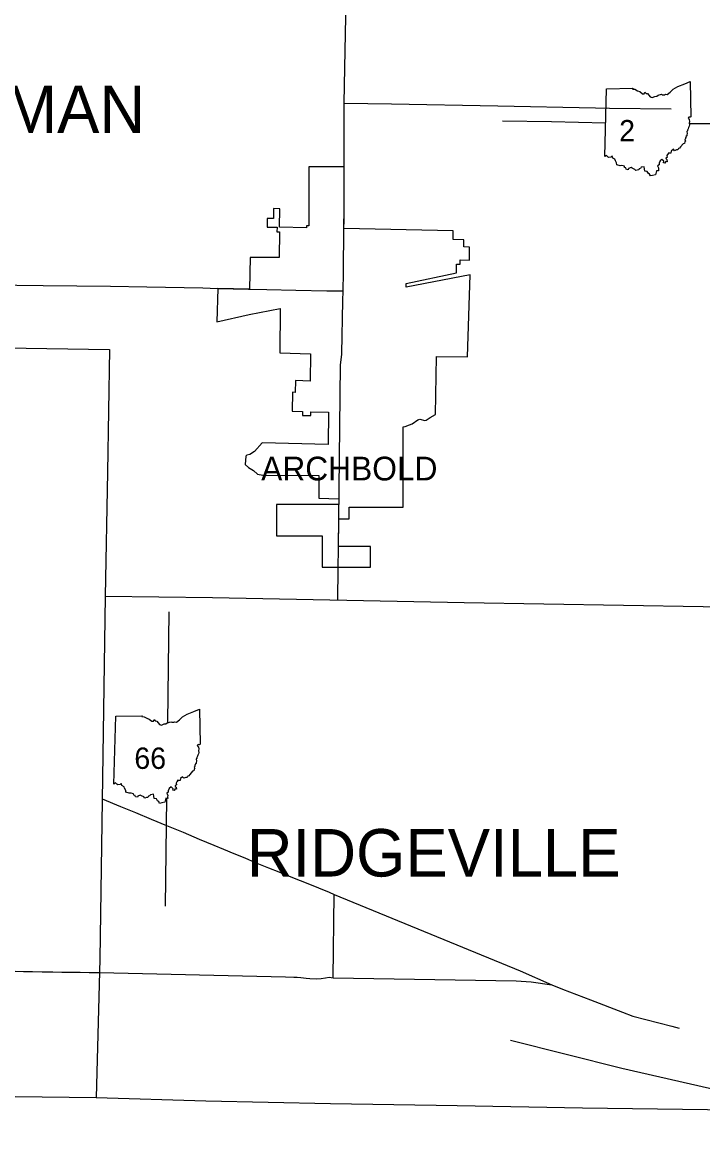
# Model space of a CAD drawing. Extents: x -232 to 448, y 619 to 1059.
# Drawn here: x -55.4 to -25.97, y 848.36 to 896.53 of the extents above; entities that cross this region are included whole.
import ezdxf

# ---------------------------------------------------------------- set-up
doc = ezdxf.new("R2010")
doc.units = 0
doc.layers.add('Default', color=7, linetype='Continuous')

msp = doc.modelspace()

# ---------------------------------------------------------------- linework, layer by layer
at = {"layer": 'Default'}
for p, q in [((-30.21, 890.731), (-30.128, 893.66)), ((-30.21, 890.731), (-30.128, 893.66)), ((-44.534, 888.477), (-44.54, 888.054)), ((-44.267, 888.473), (-44.534, 888.477)), ((-44.278, 887.672), (-44.267, 888.473)), ((-44.383, 887.674), (-44.385, 887.481)), ((-44.385, 887.481), (-44.281, 887.479)), ((-44.281, 887.479), (-44.295, 886.361)), ((-46.991, 883.585), (-45.585, 883.897)), ((-43.282, 879.709), (-43.284, 879.541)), ((-43.284, 879.541), (-42.919, 879.538)), ((-42.919, 879.538), (-42.918, 879.697)), ((-42.918, 879.697), (-42.161, 879.671)), ((-38.928, 875.564), (-38.928, 879.051)), ((-45.019, 878.35), (-45.355, 877.976)), ((-42.166, 878.284), (-45.019, 878.35)), ((-45.692, 877.819), (-45.738, 877.776)), ((-45.556, 877.846), (-45.692, 877.819)), ((-45.355, 877.976), (-45.556, 877.846)), ((-45.738, 877.776), (-45.757, 877.421)), ((-45.757, 877.421), (-45.617, 877.291)), ((-45.617, 877.291), (-45.393, 877.151)), ((-45.393, 877.151), (-45.231, 876.997)), ((-45.231, 876.997), (-44.992, 876.961)), ((-44.992, 876.961), (-42.573, 876.947)), ((-42.573, 876.947), (-42.573, 875.957)), ((-42.573, 875.957), (-41.702, 875.931)), ((-41.256, 875.06), (-41.256, 875.564)), ((-41.256, 875.564), (-38.928, 875.564)), ((-41.712, 875.06), (-41.256, 875.06)), ((-51.436, 863.603), (-51.354, 866.532)), ((-51.436, 863.603), (-51.354, 866.532))]:
    msp.add_line(p, q, dxfattribs=at)
for points in [[(-41.476, 893.037), (-41.452, 894.56), (-41.397, 897.519), (-41.385, 898.478)], [(-30.128, 893.66), (-28.992, 893.679), (-29.01, 893.644), (-28.902, 893.636), (-28.788, 893.574), (-28.692, 893.534), (-28.574, 893.441), (-28.504, 893.442), (-28.474, 893.519), (-28.42, 893.46), (-28.356, 893.449), (-28.245, 893.309), (-28.154, 893.279), (-28.044, 893.327), (-27.962, 893.334), (-27.902, 893.382), (-27.746, 893.423), (-27.703, 893.398), (-27.62, 893.403), (-27.579, 893.421), (-27.507, 893.405), (-27.38, 893.512), (-27.25, 893.637), (-27.049, 893.756), (-26.749, 893.868), (-26.512, 893.968), (-26.478, 892.448)], [(-30.128, 893.66), (-28.992, 893.679), (-29.01, 893.644), (-28.902, 893.636), (-28.788, 893.574), (-28.692, 893.534), (-28.574, 893.441), (-28.504, 893.442), (-28.474, 893.519), (-28.42, 893.46), (-28.356, 893.449), (-28.245, 893.309), (-28.154, 893.279), (-28.044, 893.327), (-27.962, 893.334), (-27.902, 893.382), (-27.746, 893.423), (-27.703, 893.398), (-27.62, 893.403), (-27.579, 893.421), (-27.507, 893.405), (-27.38, 893.512), (-27.25, 893.637), (-27.049, 893.756), (-26.749, 893.868), (-26.512, 893.968), (-26.478, 892.448)], [(-41.475, 890.238), (-41.473, 890.665), (-41.478, 892.503), (-41.476, 893.037)], [(-41.476, 893.037), (-39.437, 893.009), (-34.838, 892.926), (-30.61, 892.834), (-30.009, 892.826)], [(-30.009, 892.826), (-27.335, 892.793)], [(-34.637, 892.276), (-32.508, 892.249), (-30.169, 892.193)], [(-26.478, 892.448), (-26.513, 892.427), (-26.567, 892.437), (-26.604, 892.394), (-26.559, 892.323), (-26.537, 892.248), (-26.556, 892.165), (-26.537, 892.097), (-26.55, 892.04), (-26.584, 891.983), (-26.596, 891.929), (-26.625, 891.872), (-26.623, 891.84), (-26.651, 891.814), (-26.646, 891.719), (-26.66, 891.666), (-26.655, 891.621), (-26.7, 891.609), (-26.689, 891.572), (-26.718, 891.543), (-26.712, 891.493), (-26.744, 891.461), (-26.713, 891.397), (-26.738, 891.377), (-26.759, 891.299), (-26.817, 891.284), (-26.933, 891.142), (-26.973, 891.088), (-27.019, 891.075), (-27.044, 891.02), (-27.101, 891.019), (-27.186, 890.981), (-27.241, 891.047), (-27.338, 890.968), (-27.349, 890.877), (-27.471, 890.879), (-27.467, 890.833), (-27.494, 890.82), (-27.519, 890.774), (-27.504, 890.691), (-27.562, 890.67), (-27.555, 890.623), (-27.518, 890.594), (-27.502, 890.502), (-27.562, 890.521), (-27.612, 890.444), (-27.664, 890.462), (-27.647, 890.527), (-27.733, 890.605), (-27.815, 890.543), (-27.858, 890.442), (-27.858, 890.375), (-27.919, 890.334), (-27.88, 890.239), (-27.888, 890.173), (-27.886, 890.111), (-27.963, 890.113), (-28.009, 889.945)], [(-26.478, 892.448), (-26.513, 892.427), (-26.567, 892.437), (-26.604, 892.394), (-26.559, 892.323), (-26.537, 892.248), (-26.556, 892.165), (-26.537, 892.097), (-26.55, 892.04), (-26.584, 891.983), (-26.596, 891.929), (-26.625, 891.872), (-26.623, 891.84), (-26.651, 891.814), (-26.646, 891.719), (-26.66, 891.666), (-26.655, 891.621), (-26.7, 891.609), (-26.689, 891.572), (-26.718, 891.543), (-26.712, 891.493), (-26.744, 891.461), (-26.713, 891.397), (-26.738, 891.377), (-26.759, 891.299), (-26.817, 891.284), (-26.933, 891.142), (-26.973, 891.088), (-27.019, 891.075), (-27.044, 891.02), (-27.101, 891.019), (-27.186, 890.981), (-27.241, 891.047), (-27.338, 890.968), (-27.349, 890.877), (-27.471, 890.879), (-27.467, 890.833), (-27.494, 890.82), (-27.519, 890.774), (-27.504, 890.691), (-27.562, 890.67), (-27.555, 890.623), (-27.518, 890.594), (-27.502, 890.502), (-27.562, 890.521), (-27.612, 890.444), (-27.664, 890.462), (-27.647, 890.527), (-27.733, 890.605), (-27.815, 890.543), (-27.858, 890.442), (-27.858, 890.375), (-27.919, 890.334), (-27.88, 890.239), (-27.888, 890.173), (-27.886, 890.111), (-27.963, 890.113), (-28.009, 889.945)], [(-26.556, 892.164), (-24.693, 892.155), (-22.517, 892.128), (-20.083, 892.102), (-16.53, 892.06)], [(-28.009, 889.945), (-28.141, 889.913), (-28.233, 889.894), (-28.266, 889.97), (-28.332, 890.01), (-28.375, 890.087), (-28.469, 890.098), (-28.492, 890.203), (-28.502, 890.289), (-28.631, 890.268), (-28.667, 890.216), (-28.713, 890.202), (-28.739, 890.149), (-28.802, 890.144), (-28.869, 890.119), (-28.913, 890.171), (-29.023, 890.223), (-29.072, 890.25), (-29.175, 890.208), (-29.197, 890.159), (-29.28, 890.181), (-29.299, 890.236), (-29.349, 890.252), (-29.36, 890.311), (-29.466, 890.342), (-29.547, 890.329), (-29.691, 890.376), (-29.699, 890.453), (-29.748, 890.547), (-29.774, 890.612), (-29.864, 890.661), (-29.883, 890.738), (-29.912, 890.736), (-29.938, 890.705), (-30.039, 890.69), (-30.079, 890.722), (-30.136, 890.776), (-30.21, 890.731)], [(-28.009, 889.945), (-28.141, 889.913), (-28.233, 889.894), (-28.266, 889.97), (-28.332, 890.01), (-28.375, 890.087), (-28.469, 890.098), (-28.492, 890.203), (-28.502, 890.289), (-28.631, 890.268), (-28.667, 890.216), (-28.713, 890.202), (-28.739, 890.149), (-28.802, 890.144), (-28.869, 890.119), (-28.913, 890.171), (-29.023, 890.223), (-29.072, 890.25), (-29.175, 890.208), (-29.197, 890.159), (-29.28, 890.181), (-29.299, 890.236), (-29.349, 890.252), (-29.36, 890.311), (-29.466, 890.342), (-29.547, 890.329), (-29.691, 890.376), (-29.699, 890.453), (-29.748, 890.547), (-29.774, 890.612), (-29.864, 890.661), (-29.883, 890.738), (-29.912, 890.736), (-29.938, 890.705), (-30.039, 890.69), (-30.079, 890.722), (-30.136, 890.776), (-30.21, 890.731)], [(-41.475, 890.283), (-43.003, 890.283), (-43.003, 887.728)], [(-41.489, 887.495), (-41.483, 888.094), (-41.476, 890.073)], [(-41.488, 887.618), (-41.479, 888.484), (-41.476, 889.785), (-41.475, 890.283)], [(-41.476, 890.073), (-41.475, 890.183)], [(-41.475, 890.183), (-41.475, 890.238)], [(-44.54, 888.054), (-44.814, 888.054), (-44.814, 887.682)], [(-44.814, 887.682), (-44.383, 887.674)], [(-43.114, 887.652), (-44.278, 887.672)], [(-43.003, 887.728), (-43.114, 887.728), (-43.114, 887.652)], [(-41.51, 885.705), (-41.503, 886.236), (-41.493, 887.11), (-41.489, 887.495)], [(-36.758, 887.517), (-41.488, 887.618)], [(-36.053, 886.814), (-36.302, 886.822), (-36.302, 887.13), (-36.758, 887.146), (-36.758, 887.517)], [(-36.057, 886.244), (-36.053, 886.814)], [(-44.295, 886.361), (-45.55, 886.362), (-45.569, 884.994)], [(-38.79, 885.243), (-36.622, 885.697), (-36.622, 886.076), (-36.468, 886.073), (-36.468, 886.258), (-36.057, 886.244)], [(-41.521, 884.923), (-41.51, 885.705)], [(-36.028, 885.62), (-38.79, 885.075), (-38.79, 885.243)], [(-36.149, 882.065), (-36.028, 885.62)], [(-62.411, 885.218), (-60.819, 885.234), (-59.99, 885.206), (-59.711, 885.198), (-57.944, 885.192), (-54.499, 885.158), (-51.585, 885.128), (-50.017, 885.099), (-47.59, 885.046), (-46.955, 885.03)], [(-46.941, 885.029), (-46.991, 883.585)], [(-46.955, 885.03), (-45.609, 884.995)], [(-45.569, 884.994), (-46.941, 885.029)], [(-45.609, 884.995), (-44.818, 884.974), (-43.564, 884.951)], [(-43.564, 884.951), (-42.225, 884.925), (-41.521, 884.923)], [(-41.531, 884.49), (-41.521, 884.923)], [(-45.585, 883.897), (-44.241, 884.153), (-44.266, 882.238)], [(-41.585, 882.217), (-41.531, 884.49)], [(-62.463, 882.554), (-51.629, 882.386), (-51.711, 877.081), (-51.822, 871.726)], [(-44.266, 882.238), (-42.936, 882.205), (-42.947, 881.019)], [(-41.712, 875.023), (-41.641, 881.725), (-41.586, 882.168), (-41.585, 882.217)], [(-37.532, 879.571), (-37.488, 882.091)], [(-37.488, 882.091), (-36.149, 882.065)], [(-42.947, 881.019), (-43.589, 881.041), (-43.598, 880.533), (-43.709, 880.537), (-43.723, 879.725), (-43.282, 879.709)], [(-42.161, 879.671), (-42.166, 878.284)], [(-38.928, 879.051), (-38.836, 879.056), (-38.655, 879.135), (-38.535, 879.168), (-38.293, 879.342), (-38.199, 879.374), (-37.995, 879.324), (-37.929, 879.339), (-37.754, 879.441), (-37.532, 879.571)], [(-41.702, 875.931), (-41.705, 875.689)], [(-41.705, 875.689), (-44.411, 875.689), (-44.411, 874.33), (-42.432, 874.33)], [(-41.725, 873.833), (-41.712, 875.023)], [(-41.724, 873.869), (-41.712, 875.06)], [(-42.432, 874.33), (-42.432, 872.973)], [(-42.432, 872.973), (-40.344, 872.973), (-40.344, 873.869), (-41.724, 873.869)], [(-41.735, 872.912), (-41.725, 873.833)], [(-41.749, 871.559), (-41.735, 872.912)], [(-51.822, 871.726), (-52.048, 856.032), (-52.202, 850.044)], [(-51.822, 871.726), (-47.172, 871.662), (-36.289, 871.455), (-25.953, 871.278), (-20.047, 871.155)], [(-49.111, 866.258), (-49.051, 871.042)], [(-51.354, 866.532), (-50.218, 866.551), (-50.235, 866.516), (-50.128, 866.508), (-50.014, 866.446), (-49.918, 866.406), (-49.8, 866.313), (-49.73, 866.314), (-49.7, 866.39), (-49.646, 866.331), (-49.582, 866.321), (-49.471, 866.181), (-49.38, 866.15), (-49.27, 866.198), (-49.188, 866.206), (-49.128, 866.254), (-48.972, 866.294), (-48.929, 866.27), (-48.846, 866.275), (-48.805, 866.293), (-48.733, 866.277), (-48.606, 866.383), (-48.476, 866.509), (-48.275, 866.627), (-47.975, 866.74), (-47.738, 866.84), (-47.704, 865.32)], [(-51.354, 866.532), (-50.218, 866.551), (-50.235, 866.516), (-50.128, 866.508), (-50.014, 866.446), (-49.918, 866.406), (-49.8, 866.313), (-49.73, 866.314), (-49.7, 866.39), (-49.646, 866.331), (-49.582, 866.321), (-49.471, 866.181), (-49.38, 866.15), (-49.27, 866.198), (-49.188, 866.206), (-49.128, 866.254), (-48.972, 866.294), (-48.929, 866.27), (-48.846, 866.275), (-48.805, 866.293), (-48.733, 866.277), (-48.606, 866.383), (-48.476, 866.509), (-48.275, 866.627), (-47.975, 866.74), (-47.738, 866.84), (-47.704, 865.32)], [(-47.704, 865.32), (-47.739, 865.299), (-47.793, 865.309), (-47.83, 865.266), (-47.784, 865.195), (-47.763, 865.12), (-47.782, 865.037), (-47.763, 864.969), (-47.776, 864.912), (-47.81, 864.855), (-47.822, 864.8), (-47.851, 864.743), (-47.849, 864.711), (-47.877, 864.686), (-47.872, 864.591), (-47.886, 864.538), (-47.881, 864.493), (-47.926, 864.481), (-47.915, 864.443), (-47.944, 864.414), (-47.938, 864.364), (-47.97, 864.333), (-47.939, 864.269), (-47.964, 864.249), (-47.985, 864.171), (-48.043, 864.155), (-48.158, 864.014), (-48.199, 863.96), (-48.245, 863.947), (-48.27, 863.891), (-48.327, 863.891), (-48.412, 863.853), (-48.467, 863.919), (-48.564, 863.84), (-48.575, 863.748), (-48.697, 863.751), (-48.693, 863.705), (-48.72, 863.692), (-48.745, 863.645), (-48.73, 863.563), (-48.787, 863.542), (-48.781, 863.495), (-48.744, 863.465), (-48.728, 863.374), (-48.788, 863.393), (-48.838, 863.316), (-48.889, 863.334), (-48.873, 863.399), (-48.959, 863.477), (-49.041, 863.415), (-49.084, 863.314), (-49.084, 863.247), (-49.145, 863.206), (-49.106, 863.111), (-49.113, 863.045), (-49.112, 862.983), (-49.189, 862.985), (-49.235, 862.817)], [(-47.704, 865.32), (-47.739, 865.299), (-47.793, 865.309), (-47.83, 865.266), (-47.784, 865.195), (-47.763, 865.12), (-47.782, 865.037), (-47.763, 864.969), (-47.776, 864.912), (-47.81, 864.855), (-47.822, 864.8), (-47.851, 864.743), (-47.849, 864.711), (-47.877, 864.686), (-47.872, 864.591), (-47.886, 864.538), (-47.881, 864.493), (-47.926, 864.481), (-47.915, 864.443), (-47.944, 864.414), (-47.938, 864.364), (-47.97, 864.333), (-47.939, 864.269), (-47.964, 864.249), (-47.985, 864.171), (-48.043, 864.155), (-48.158, 864.014), (-48.199, 863.96), (-48.245, 863.947), (-48.27, 863.891), (-48.327, 863.891), (-48.412, 863.853), (-48.467, 863.919), (-48.564, 863.84), (-48.575, 863.748), (-48.697, 863.751), (-48.693, 863.705), (-48.72, 863.692), (-48.745, 863.645), (-48.73, 863.563), (-48.787, 863.542), (-48.781, 863.495), (-48.744, 863.465), (-48.728, 863.374), (-48.788, 863.393), (-48.838, 863.316), (-48.889, 863.334), (-48.873, 863.399), (-48.959, 863.477), (-49.041, 863.415), (-49.084, 863.314), (-49.084, 863.247), (-49.145, 863.206), (-49.106, 863.111), (-49.113, 863.045), (-49.112, 862.983), (-49.189, 862.985), (-49.235, 862.817)], [(-49.235, 862.817), (-49.367, 862.785), (-49.459, 862.766), (-49.492, 862.842), (-49.558, 862.882), (-49.601, 862.959), (-49.695, 862.97), (-49.717, 863.075), (-49.728, 863.161), (-49.857, 863.14), (-49.893, 863.087), (-49.939, 863.073), (-49.965, 863.021), (-50.028, 863.016), (-50.095, 862.991), (-50.139, 863.043), (-50.249, 863.095), (-50.298, 863.122), (-50.401, 863.08), (-50.423, 863.031), (-50.505, 863.053), (-50.525, 863.108), (-50.574, 863.124), (-50.585, 863.182), (-50.692, 863.214), (-50.773, 863.201), (-50.917, 863.248), (-50.925, 863.325), (-50.974, 863.418), (-51, 863.483), (-51.09, 863.533), (-51.109, 863.61), (-51.138, 863.608), (-51.164, 863.577), (-51.265, 863.562), (-51.305, 863.594), (-51.362, 863.648), (-51.436, 863.603)], [(-49.235, 862.817), (-49.367, 862.785), (-49.459, 862.766), (-49.492, 862.842), (-49.558, 862.882), (-49.601, 862.959), (-49.695, 862.97), (-49.717, 863.075), (-49.728, 863.161), (-49.857, 863.14), (-49.893, 863.087), (-49.939, 863.073), (-49.965, 863.021), (-50.028, 863.016), (-50.095, 862.991), (-50.139, 863.043), (-50.249, 863.095), (-50.298, 863.122), (-50.401, 863.08), (-50.423, 863.031), (-50.505, 863.053), (-50.525, 863.108), (-50.574, 863.124), (-50.585, 863.182), (-50.692, 863.214), (-50.773, 863.201), (-50.917, 863.248), (-50.925, 863.325), (-50.974, 863.418), (-51, 863.483), (-51.09, 863.533), (-51.109, 863.61), (-51.138, 863.608), (-51.164, 863.577), (-51.265, 863.562), (-51.305, 863.594), (-51.362, 863.648), (-51.436, 863.603)], [(-51.948, 862.967), (-51.146, 862.631), (-50.498, 862.364), (-49.829, 862.09), (-49.156, 861.802), (-48.442, 861.514), (-47.751, 861.217), (-47.112, 860.964), (-46.704, 860.793), (-46.256, 860.598), (-45.778, 860.406), (-45.322, 860.203), (-44.748, 859.986), (-44.301, 859.804), (-43.708, 859.564), (-43.055, 859.305), (-42.594, 859.114), (-42.133, 858.927), (-41.909, 858.833), (-33.871, 855.527), (-32.498, 854.914)], [(-49.21, 858.316), (-49.152, 862.984)], [(-41.955, 855.227), (-41.909, 858.833)], [(-55.709, 855.507), (-55.349, 855.5), (-54.952, 855.494), (-54.537, 855.487), (-54.085, 855.481), (-53.689, 855.473), (-53.276, 855.471), (-52.897, 855.463), (-52.509, 855.457), (-52.063, 855.454)], [(-52.063, 855.454), (-44.018, 855.265), (-43.66, 855.255), (-43.51, 855.25), (-43.346, 855.232), (-43.124, 855.204), (-42.964, 855.194), (-42.694, 855.178), (-42.466, 855.194), (-42.292, 855.223), (-42.129, 855.248), (-41.955, 855.227)], [(-41.955, 855.227), (-34.038, 855.09), (-33.397, 855.054), (-32.498, 854.914)], [(-32.498, 854.914), (-32.04, 854.738)], [(-32.04, 854.738), (-30.82, 854.27), (-29.447, 853.742)], [(-29.447, 853.742), (-28.99, 853.566), (-27.304, 853.128), (-26.987, 853.048)], [(-34.288, 852.531), (-29.472, 851.316), (-24.861, 850.267), (-21.469, 849.465), (-21.169, 849.233), (-20.275, 848.355)], [(-85.18, 850.564), (-75.508, 850.389), (-73.913, 850.374), (-69.334, 850.268), (-67.533, 850.285), (-61.557, 850.169), (-52.202, 850.044)], [(-52.202, 850.044), (-47.466, 849.91), (-42.069, 849.794), (-36.596, 849.701), (-31.17, 849.597), (-20.351, 849.462)]]:
    msp.add_lwpolyline(points, dxfattribs=at)

# ---------------------------------------------------------------- texts
for s, height, p in [('GERMAN', 2.052, (-62.127, 891.747)), (' 2 ', 0.9234, (-29.928, 891.384)), ('ARCHBOLD', 1.026, (-45.067, 876.727)), ('66', 0.9234, (-50.554, 864.256)), ('RIDGEVILLE', 2.052, (-45.689, 859.603))]:
    msp.add_text(s, height=height, dxfattribs=at).set_placement(p)

doc.saveas('drawing.dxf')
